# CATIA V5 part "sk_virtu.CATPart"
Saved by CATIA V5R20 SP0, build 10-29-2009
Part number: sk_virtu
Publications: "Point.1", "Point.3", "Droite.1", "Droite.2", "Droite.3", "Plan.1", "Plan.2"
Bounding box of the stored display mesh (mm): x -20 to 20, y 150 to 153.743, z 0 to 69.9
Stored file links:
  D:\Dropbox\IAO_2011\MMS_GR2\IAO_2011_1495_fpittorino\fpittorino_IAO\IAO_2011_1495_fpittorino\sk_virtu.CATPart
  D:\Dropbox\IAO_2011\MMS_GR2\IAO_2011_1495_fpittorino\fpittorino_IAO\IAO_2011_1495_fpittorino\Product3.CATProduct
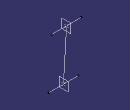
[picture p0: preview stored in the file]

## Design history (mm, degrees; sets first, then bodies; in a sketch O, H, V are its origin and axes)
Set1
  Point1: linked copy from another document
  Point2: linked copy from another document
Body1 (main body)
  Point3: (0, 0, 0), relative to Point1
  Point4: (0, 0, 0), relative to Point2
  Line1: type PtPt, FirstPoint Point4, SecondPoint Point3
  Line2: type Normal, RefPoint Point4, RefSkin yz-plane, Start -20, End 20
  Line3: type Normal, RefPoint Point3, RefSkin yz-plane, Start -20, End 20
  Plane1: type Normal, Curve Line2, RefPoint Point4
  Plane2: type Normal, Curve Line3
